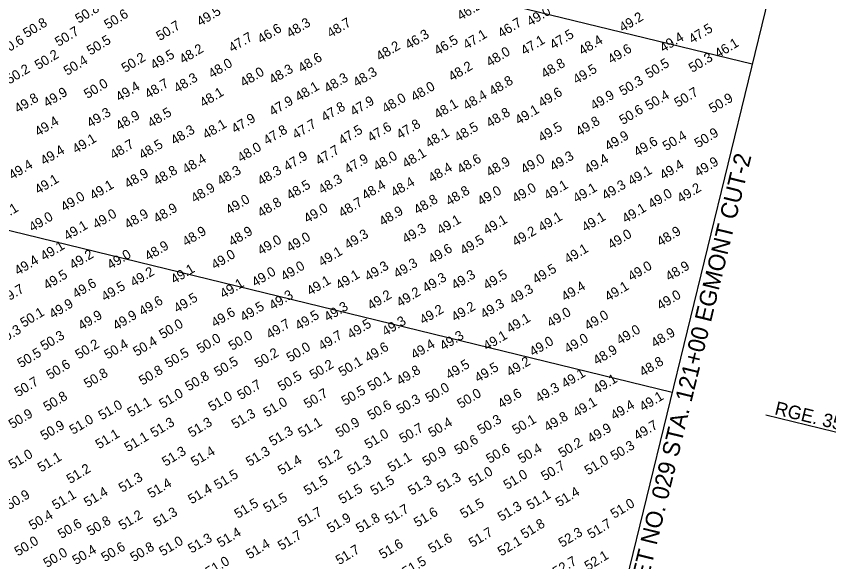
# Model space of a CAD drawing. Extents: x 412170 to 417250, y 1187847 to 1192192.
# Drawn here: x 415416 to 416259, y 1189506 to 1190071 of the extents above; entities that cross this region are included whole.
import ezdxf

# ---------------------------------------------------------------- set-up
doc = ezdxf.new("R2010")
doc.units = 0
for name, color, linetype in [('C-CHAN-CNTR', 7, 'Continuous'), ('C-CHAN-POIT', 7, 'Continuous'), ('V-ALGN-TEXT', 7, 'Continuous'), ('V-ANNO-MATC', 7, 'Continuous'), ('V-ANNO-MATC-IDEN', 7, 'Continuous'), ('V-TOPO-SOUN', 7, 'Continuous')]:
    doc.layers.add(name, color=color, linetype=linetype)

msp = doc.modelspace()

# ---------------------------------------------------------------- linework, layer by layer
at = {"layer": 'C-CHAN-CNTR'}
msp.add_line((413181.75, 1190392.1), (416096.33, 1189681.31), dxfattribs=at)
at = {"layer": 'C-CHAN-POIT'}
msp.add_line((415596.44, 1190163.48), (416179.26, 1190021.35), dxfattribs=at)
at = {"layer": 'V-ALGN-TEXT'}
msp.add_line((416193.48, 1189657.62), (416290.64, 1189633.93), dxfattribs=at)
at = {"layer": 'V-ANNO-MATC'}
msp.add_line((416300.29, 1190517.63), (415930.48, 1189001.24), dxfattribs=at)

# ---------------------------------------------------------------- texts
at = {"layer": 'V-ALGN-TEXT'}
msp.add_text('RGE. 350', height=13.92, rotation=346.29456, dxfattribs=at).set_placement((416201.7, 1189658.48))
at = {"layer": 'V-ANNO-MATC-IDEN'}
msp.add_text('MATCHLINE SHEET NO. 029 STA. 121+00 EGMONT CUT-2', height=17.52, rotation=76.29456, dxfattribs=at).set_placement((416026.36, 1189301.95))
at = {"layer": 'V-TOPO-SOUN'}
for s, p in [('50.8 ', (415481.09, 1190062.99)), ('49.5 ', (415607.11, 1190059.97)), ('46.2 ', (415877.09, 1190065.98)), ('49.0 ', (415949.1, 1190059.97)), ('50.6 ', (415511.11, 1190056.99)), ('49.2 ', (416045.1, 1190053.97)), ('50.8 ', (415427.09, 1190048)), ('50.7 ', (415565.08, 1190044.98)), ('46.6 ', (415670.1, 1190041.99)), ('48.3 ', (415700.08, 1190048)), ('48.7 ', (415742.08, 1190048)), ('46.7 ', (415919.08, 1190048)), ('47.5 ', (416117.08, 1190041.99)), ('50.7 ', (415460.09, 1190038.97)), ('47.7 ', (415640.08, 1190032.97)), ('46.3 ', (415823.08, 1190035.99)), ('47.1 ', (415883.09, 1190035.99)), ('47.5 ', (415973.08, 1190035.99)), ('50.6 ', (415403.1, 1190029.98)), ('50.5 ', (415493.1, 1190029.98)), ('46.5 ', (415853.1, 1190029.98)), ('47.1 ', (415943.1, 1190029.98)), ('48.4 ', (416003.1, 1190029.98)), ('49.4 ', (416087.09, 1190032.97)), ('46.1 ', (416144.08, 1190026.97)), ('48.2 ', (415589.09, 1190021)), ('48.2 ', (415793.1, 1190023.98)), ('48.0 ', (415907.11, 1190017.98)), ('49.6 ', (416033.09, 1190021)), ('50.2 ', (415439.09, 1190014.99)), ('50.4 ', (415469.08, 1190008.99)), ('50.2 ', (415529.09, 1190011.97)), ('49.5 ', (415559.11, 1190014.99)), ('48.6 ', (415712.09, 1190011.97)), ('50.3 ', (416117.08, 1190011.97)), ('50.2 ', (415409.11, 1190000)), ('48.0 ', (415619.08, 1190005.97)), ('48.3 ', (415682.11, 1190000)), ('48.2 ', (415868.1, 1190002.98)), ('48.8 ', (415964.09, 1190005.97)), ('49.5 ', (415997.1, 1190000)), ('50.5 ', (416072.1, 1190005.97)), ('48.0 ', (415652.09, 1189996.98)), ('48.3 ', (415769.08, 1189996.98)), ('50.0 ', (415490.08, 1189984.97)), ('48.7 ', (415553.1, 1189984.97)), ('48.3 ', (415583.09, 1189990.98)), ('48.3 ', (415739.09, 1189990.98)), ('48.8 ', (415910.09, 1189987.99)), ('50.3 ', (416045.1, 1189987.99)), ('49.9 ', (415448.08, 1189975.98)), ('49.4 ', (415523.08, 1189981.99)), ('48.1 ', (415610.09, 1189975.98)), ('48.1 ', (415709.11, 1189981.99)), ('48.0 ', (415829.09, 1189981.99)), ('49.6 ', (415961.11, 1189975.98)), ('50.7 ', (416102.09, 1189975.98)), ('49.8 ', (415418.1, 1189969.98)), ('47.9 ', (415682.11, 1189966.99)), ('47.9 ', (415766.1, 1189966.99)), ('48.0 ', (415799.1, 1189969.98)), ('48.4 ', (415883.09, 1189973)), ('49.9 ', (416015.08, 1189973)), ('50.4 ', (416072.1, 1189973)), ('50.9 ', (416138.11, 1189969.98)), ('47.8 ', (415736.11, 1189960.99)), ('48.1 ', (415853.1, 1189963.97)), ('50.6 ', (416045.1, 1189957.97)), ('49.3 ', (415493.1, 1189954.98)), ('48.9 ', (415523.08, 1189951.97)), ('48.5 ', (415556.09, 1189954.98)), ('48.8 ', (415907.11, 1189954.98)), ('49.1 ', (415937.09, 1189957.97)), ('49.4 ', (415439.09, 1189946)), ('48.1 ', (415613.11, 1189942.98)), ('47.9 ', (415643.1, 1189948.98)), ('47.7 ', (415706.09, 1189942.98)), ('47.8 ', (415814.09, 1189942.98)), ('49.8 ', (416000.08, 1189946)), ('48.3 ', (415580.1, 1189936.97)), ('47.8 ', (415676.1, 1189936.97)), ('47.5 ', (415754.09, 1189936.97)), ('47.6 ', (415784.11, 1189939.99)), ('48.1 ', (415844.08, 1189933.99)), ('48.5 ', (415874.1, 1189939.99)), ('49.5 ', (415961.11, 1189939.99)), ('50.9 ', (416123.08, 1189933.99)), ('49.1 ', (415478.1, 1189927.98)), ('49.9 ', (416030.1, 1189930.97)), ('49.6 ', (416060.09, 1189925)), ('50.4 ', (416090.08, 1189930.97)), ('49.4 ', (415445.1, 1189915.98)), ('48.7 ', (415517.08, 1189921.98)), ('48.5 ', (415547.1, 1189921.98)), ('48.0 ', (415649.1, 1189918.99)), ('47.7 ', (415730.1, 1189915.98)), ('47.9 ', (415697.1, 1189909.97)), ('48.0 ', (415790.08, 1189909.97)), ('48.1 ', (415820.1, 1189912.99)), ('48.6 ', (415877.09, 1189906.99)), ('49.3 ', (415973.08, 1189909.97)), ('49.4 ', (415412.09, 1189900.98)), ('48.4 ', (415592.08, 1189906.99)), ('47.9 ', (415760.09, 1189906.99)), ('48.9 ', (415907.11, 1189903.97)), ('49.0 ', (415943.1, 1189906.99)), ('49.4 ', (416009.11, 1189906.99)), ('49.4 ', (416087.09, 1189900.98)), ('49.9 ', (416123.08, 1189903.97)), ('48.9 ', (415532.11, 1189891.99)), ('48.8 ', (415562.09, 1189894.98)), ('48.3 ', (415628.1, 1189894.98)), ('48.3 ', (415670.1, 1189894.98)), ('48.4 ', (415847.1, 1189898)), ('49.1 ', (416054.09, 1189894.98)), ('49.1 ', (415439.09, 1189885.99)), ('48.3 ', (415733.09, 1189885.99)), ('48.4 ', (415808.09, 1189882.97)), ('49.1 ', (415496.08, 1189879.98)), ('48.9 ', (415601.1, 1189876.97)), ('48.5 ', (415700.08, 1189879.98)), ('48.4 ', (415778.1, 1189879.98)), ('48.8 ', (415865.08, 1189873.98)), ('49.0 ', (415898.08, 1189873.98)), ('49.0 ', (415934.11, 1189876.97)), ('49.1 ', (415967.08, 1189879.98)), ('49.1 ', (415997.1, 1189876.97)), ('49.3 ', (416027.09, 1189879.98)), ('49.2 ', (416105.1, 1189876.97)), ('49.0 ', (415466.1, 1189867.98)), ('49.0 ', (415637.09, 1189864.99)), ('49.0 ', (416075.08, 1189871)), ('48.8 ', (415670.1, 1189861.97)), ('48.7 ', (415754.09, 1189861.97)), ('48.8 ', (415832.11, 1189864.99)), ('49.1 ', (415397.1, 1189855.97)), ('49.0 ', (415499.1, 1189850)), ('48.9 ', (415532.11, 1189850)), ('48.9 ', (415562.09, 1189855.97)), ('49.0 ', (415718.1, 1189855.97)), ('48.9 ', (415796.08, 1189852.98)), ('49.1 ', (416048.08, 1189855.97)), ('49.0 ', (415433.09, 1189846.98)), ('49.1 ', (415856.09, 1189843.99)), ('49.1 ', (415904.09, 1189843.99)), ('49.1 ', (415961.11, 1189846.98)), ('49.1 ', (416006.09, 1189846.98)), ('49.1 ', (415469.08, 1189837.99)), ('48.9 ', (415592.08, 1189831.99)), ('48.9 ', (415640.08, 1189831.99)), ('49.3 ', (415820.1, 1189834.97)), ('49.2 ', (415934.11, 1189831.99)), ('48.9 ', (416084.11, 1189831.99)), ('49.0 ', (415670.1, 1189823)), ('49.0 ', (415700.08, 1189825.98)), ('49.3 ', (415760.09, 1189828.97)), ('49.5 ', (415880.1, 1189823)), ('49.0 ', (416033.09, 1189828.97)), ('49.1 ', (415445.1, 1189816.99)), ('48.9 ', (415553.1, 1189816.99)), ('49.2 ', (415475.09, 1189807.97)), ('49.0 ', (415514.09, 1189807.97)), ('49.0 ', (415622.1, 1189807.97)), ('49.1 ', (415733.09, 1189810.99)), ('49.6 ', (415847.1, 1189813.97)), ('49.1 ', (415988.11, 1189813.97)), ('49.4 ', (415418.1, 1189801.97)), ('49.3 ', (415811.11, 1189798.98)), ('49.2 ', (415538.11, 1189789.99)), ('49.1 ', (415580.1, 1189792.98)), ('49.0 ', (415664.09, 1189789.99)), ('49.0 ', (415694.08, 1189796)), ('49.3 ', (415781.09, 1189796)), ('49.5 ', (415955.1, 1189792.98)), ('49.0 ', (416054.09, 1189796)), ('48.9 ', (416093.1, 1189796)), ('49.5 ', (415448.08, 1189786.97)), ('49.1 ', (415751.1, 1189786.97)), ('49.3 ', (415841.1, 1189783.99)), ('49.3 ', (415871.08, 1189786.97)), ('49.5 ', (415904.09, 1189786.97)), ('49.7 ', (415403.1, 1189771.98)), ('49.6 ', (415478.1, 1189777.98)), ('49.5 ', (415508.09, 1189775)), ('49.1 ', (415631.09, 1189777.98)), ('49.1 ', (415721.08, 1189780.97)), ('49.4 ', (415985.09, 1189775)), ('49.1 ', (416030.1, 1189775)), ('49.3 ', (415682.11, 1189765.98)), ('49.2 ', (415784.11, 1189765.98)), ('49.2 ', (415814.09, 1189768.99)), ('49.3 ', (415931.09, 1189771.98)), ('49.0 ', (416084.11, 1189765.98)), ('49.9 ', (415454.09, 1189756.99)), ('49.6 ', (415547.1, 1189759.97)), ('49.5 ', (415583.09, 1189762.99)), ('49.3 ', (415901.1, 1189756.99)), ('50.1 ', (415424.1, 1189748)), ('49.6 ', (415622.1, 1189748)), ('49.5 ', (415652.09, 1189753.97)), ('49.3 ', (415739.09, 1189753.97)), ('49.2 ', (415838.11, 1189750.98)), ('49.2 ', (415871.08, 1189753.97)), ('49.0 ', (415970.1, 1189748)), ('49.9 ', (415484.11, 1189744.98)), ('49.9 ', (415520.1, 1189744.98)), ('49.5 ', (415709.11, 1189744.98)), ('49.3 ', (415799.1, 1189738.97)), ('49.1 ', (415928.1, 1189741.99)), ('49.0 ', (416009.11, 1189744.98)), ('50.0 ', (415568.1, 1189735.99)), ('49.7 ', (415679.09, 1189735.99)), ('49.5 ', (415763.11, 1189735.99)), ('50.3 ', (415400.09, 1189729.99)), ('50.3 ', (415445.1, 1189723.98)), ('50.0 ', (415640.08, 1189723.98)), ('49.7 ', (415733.09, 1189723.98)), ('49.3 ', (415859.11, 1189723.98)), ('49.1 ', (415904.09, 1189723.98)), ('49.0 ', (416042.08, 1189729.99)), ('48.9 ', (416078.1, 1189726.97)), ('50.2 ', (415481.09, 1189714.99)), ('50.4 ', (415511.11, 1189714.99)), ('50.4 ', (415541.1, 1189717.98)), ('50.0 ', (415607.11, 1189721)), ('49.4 ', (415829.09, 1189714.99)), ('49.0 ', (415952.09, 1189717.98)), ('49.0 ', (415988.11, 1189721)), ('50.5 ', (415421.08, 1189705.97)), ('50.5 ', (415574.1, 1189705.97)), ('50.2 ', (415667.08, 1189705.97)), ('50.0 ', (415700.08, 1189711.97)), ('49.6 ', (415781.09, 1189711.97)), ('48.9 ', (416018.1, 1189708.99)), ('50.5 ', (415625.09, 1189696.98)), ('49.2 ', (415928.1, 1189696.98)), ('48.8 ', (416066.09, 1189696.98)), ('50.6 ', (415451.1, 1189693.99)), ('50.2 ', (415724.1, 1189693.99)), ('50.1 ', (415754.09, 1189696.98)), ('49.5 ', (415865.08, 1189693.99)), ('49.5 ', (415895.1, 1189690.98)), ('50.8 ', (415490.08, 1189684.97)), ('50.8 ', (415547.1, 1189687.99)), ('50.8 ', (415595.1, 1189681.99)), ('50.5 ', (415691.1, 1189681.99)), ('50.1 ', (415784.11, 1189681.99)), ('49.8 ', (415814.09, 1189687.99)), ('49.1 ', (415985.09, 1189684.97)), ('50.7 ', (415418.1, 1189675.98)), ('50.7 ', (415649.1, 1189673)), ('49.1 ', (416018.1, 1189678.97)), ('51.0 ', (415568.1, 1189663.97)), ('50.7 ', (415718.1, 1189663.97)), ('50.5 ', (415757.11, 1189666.99)), ('50.0 ', (415844.08, 1189669.98)), ('50.0 ', (415877.09, 1189663.97)), ('49.6 ', (415919.08, 1189663.97)), ('49.3 ', (415958.09, 1189669.98)), ('50.8 ', (415448.08, 1189660.99)), ('51.1 ', (415535.09, 1189654.99)), ('51.0 ', (415619.08, 1189660.99)), ('51.0 ', (415676.1, 1189654.99)), ('50.3 ', (415814.09, 1189657.97)), ('49.1 ', (415997.1, 1189654.99)), ('49.1 ', (416066.09, 1189660.99)), ('51.0 ', (415505.1, 1189651.97)), ('50.6 ', (415784.11, 1189651.97)), ('49.4 ', (416036.11, 1189651.97)), ('50.9 ', (415412.09, 1189642.98)), ('51.3 ', (415643.1, 1189642.98)), ('49.8 ', (415967.08, 1189639.99)), ('50.9 ', (415445.1, 1189630.97)), ('51.0 ', (415475.09, 1189636.97)), ('51.3 ', (415559.11, 1189633.99)), ('51.3 ', (415598.08, 1189633.99)), ('51.1 ', (415712.09, 1189633.99)), ('50.9 ', (415751.1, 1189633.99)), ('50.4 ', (415847.1, 1189633.99)), ('50.3 ', (415898.08, 1189636.97)), ('50.1 ', (415934.11, 1189636.97)), ('49.7 ', (416060.09, 1189630.97)), ('51.1 ', (415502.09, 1189621.98)), ('51.3 ', (415682.11, 1189625)), ('51.0 ', (415781.09, 1189621.98)), ('50.7 ', (415817.08, 1189627.98)), ('49.9 ', (416012.09, 1189627.98)), ('51.1 ', (415532.11, 1189618.99)), ('50.6 ', (415874.1, 1189615.98)), ('50.2 ', (415982.11, 1189612.99)), ('51.4 ', (415601.1, 1189603.97)), ('50.9 ', (415841.1, 1189603.97)), ('50.6 ', (415907.11, 1189606.99)), ('50.4 ', (415940.08, 1189606.99)), ('50.3 ', (416036.11, 1189609.97)), ('51.0 ', (415412.09, 1189600.98)), ('51.1 ', (415442.08, 1189598)), ('51.3 ', (415571.08, 1189603.97)), ('51.3 ', (415658.09, 1189603.97)), ('51.2 ', (415733.09, 1189600.98)), ('51.1 ', (415805.1, 1189598)), ('51.4 ', (415691.1, 1189594.98)), ('51.3 ', (415763.11, 1189594.98)), ('50.7 ', (415964.09, 1189588.97)), ('51.0 ', (416009.11, 1189594.98)), ('51.2 ', (415472.1, 1189585.99)), ('51.5 ', (415625.09, 1189579.99)), ('51.0 ', (415889.09, 1189582.97)), ('51.0 ', (415925.08, 1189579.99)), ('51.3 ', (415526.1, 1189576.97)), ('51.4 ', (415556.09, 1189571)), ('51.5 ', (415718.1, 1189573.98)), ('51.5 ', (415787.09, 1189573.98)), ('51.3 ', (415826.1, 1189573.98)), ('51.3 ', (415856.09, 1189576.97)), ('51.4 ', (415490.08, 1189561.97)), ('51.4 ', (415598.08, 1189564.99)), ('51.5 ', (415754.09, 1189564.99)), ('51.4 ', (415979.09, 1189561.97)), ('50.9 ', (415409.11, 1189558.99)), ('51.1 ', (415457.11, 1189558.99)), ('51.5 ', (415676.1, 1189555.97)), ('51.1 ', (415949.1, 1189558.99)), ('51.5 ', (415646.08, 1189550)), ('51.5 ', (415880.1, 1189550)), ('51.3 ', (415919.08, 1189546.98)), ('51.0 ', (416036.11, 1189550)), ('50.4 ', (415433.09, 1189537.99)), ('51.2 ', (415526.1, 1189537.99)), ('51.3 ', (415562.09, 1189540.98)), ('51.7 ', (415712.09, 1189540.98)), ('51.7 ', (415802.09, 1189543.99)), ('51.6 ', (415832.11, 1189540.98)), ('50.6 ', (415463.08, 1189528.97)), ('50.8 ', (415493.1, 1189531.99)), ('51.9 ', (415742.08, 1189534.97)), ('51.8 ', (415772.1, 1189534.97)), ('51.8 ', (415943.1, 1189528.97)), ('51.7 ', (416012.09, 1189528.97)), ('51.4 ', (415628.1, 1189519.98)), ('51.7 ', (415889.09, 1189519.98)), ('52.3 ', (415982.11, 1189519.98)), ('51.3 ', (415598.08, 1189513.98)), ('51.7 ', (415691.1, 1189516.99)), ('51.6 ', (415847.1, 1189513.98)), ('50.0 ', (415418.1, 1189510.99)), ('50.6 ', (415508.09, 1189504.99)), ('50.8 ', (415538.11, 1189504.99)), ('51.0 ', (415568.1, 1189510.99)), ('51.4 ', (415658.09, 1189507.97)), ('51.6 ', (415796.08, 1189507.97)), ('52.1 ', (415919.08, 1189510.99)), ('50.0 ', (415448.08, 1189498.98)), ('50.4 ', (415478.1, 1189501.97)), ('51.7 ', (415751.1, 1189501.97)), ('52.1 ', (416009.11, 1189496)), ('51.0 ', (415616.1, 1189489.99)), ('51.5 ', (415820.1, 1189489.99)), ('52.7 ', (415976.1, 1189489.99))]:
    msp.add_text(s, height=9.996, rotation=31.2939, dxfattribs=at).set_placement(p)

doc.saveas('drawing.dxf')
